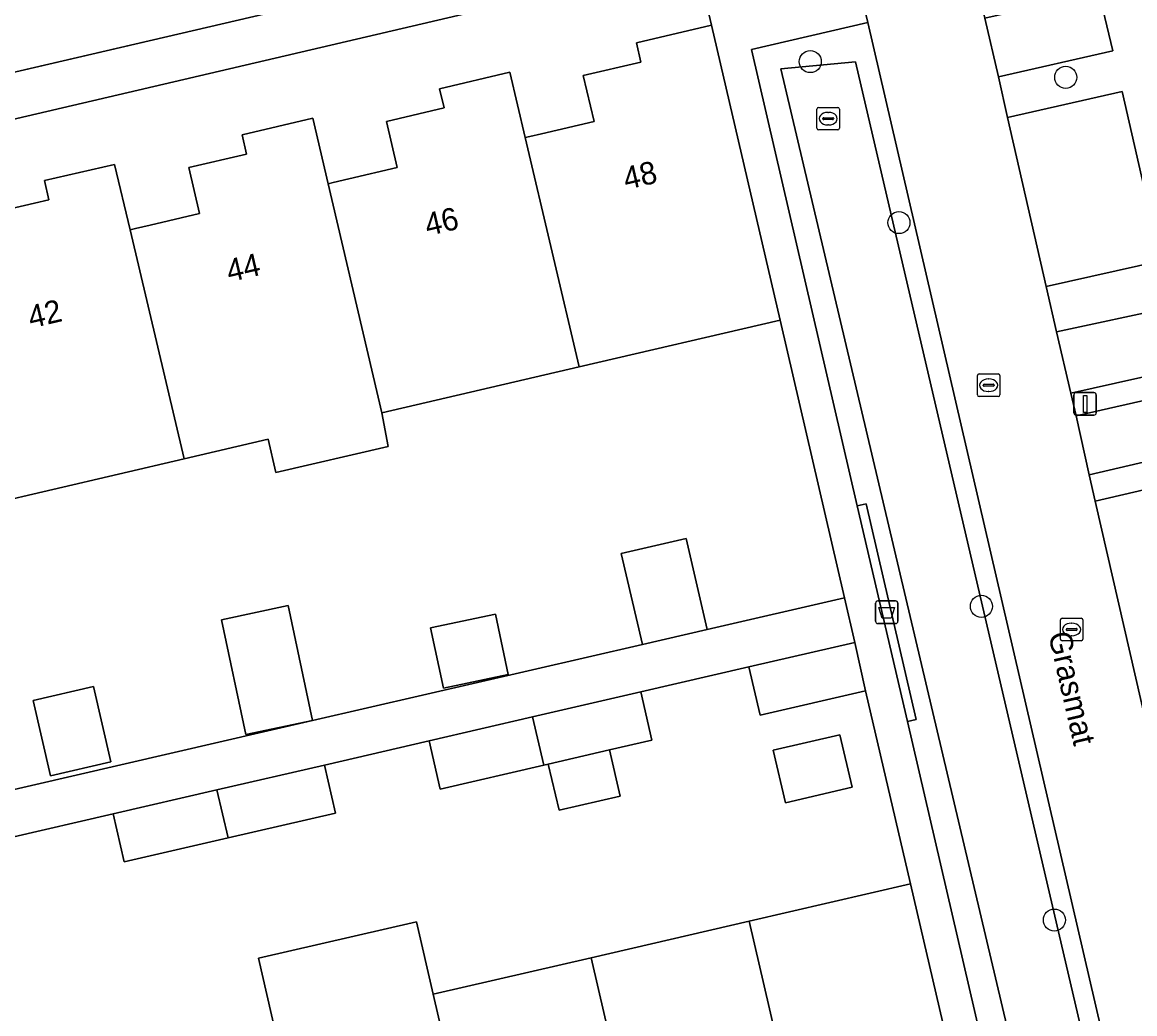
# Model space of a CAD drawing. Extents: x 156412 to 157779, y 382335 to 383768.
# Drawn here: x 156897.2 to 156946.58, y 382800.53 to 382844.52 of the extents above; entities that cross this region are included whole.
import ezdxf

# ---------------------------------------------------------------- set-up
doc = ezdxf.new("R2010")
doc.units = 0
for name, color, linetype in [('IMGEO_Afvalbak', 7, 'Continuous'), ('IMGEO_Berm_groen', 7, 'Continuous'), ('IMGEO_Boom', 7, 'Continuous'), ('IMGEO_Erf', 7, 'Continuous'), ('IMGEO_Greppel_droge_sloot', 7, 'Continuous'), ('IMGEO_Groenvoorziening', 7, 'Continuous'), ('IMGEO_Haag', 7, 'Continuous'), ('IMGEO_Kolk', 7, 'Continuous'), ('IMGEO_Lichtmast', 7, 'Continuous'), ('IMGEO_Muur', 7, 'Continuous'), ('IMGEO_Openbare_ruimte_label', 7, 'Continuous'), ('IMGEO_Pand', 7, 'Continuous'), ('IMGEO_Pand_nummerreeks', 7, 'Continuous'), ('IMGEO_Parkeervlak_open', 7, 'Continuous'), ('IMGEO_Rijbaan_lokaal_gesloten', 7, 'Continuous'), ('IMGEO_Rioolput', 7, 'Continuous'), ('IMGEO_Voetpad_open', 7, 'Continuous')]:
    doc.layers.add(name, color=color, linetype=linetype)

msp = doc.modelspace()

# ---------------------------------------------------------------- linework, layer by layer
at = {"layer": 'IMGEO_Afvalbak'}
for p, q in [((156935.078, 382817.947), (156935.078, 382818.747)), ((156935.078, 382818.747), (156935.078, 382817.947)), ((156935.178, 382818.847), (156935.968, 382818.847)), ((156935.968, 382818.847), (156935.178, 382818.847)), ((156936.068, 382818.747), (156936.068, 382817.947)), ((156936.068, 382817.947), (156936.068, 382818.747)), ((156935.968, 382817.847), (156935.178, 382817.847)), ((156935.178, 382817.847), (156935.968, 382817.847))]:
    msp.add_line(p, q, dxfattribs=at)
msp.add_lwpolyline([(156935.221, 382818.561), (156935.925, 382818.561), (156935.776, 382818.091), (156935.37, 382818.091), (156935.221, 382818.561)], dxfattribs=at)
for centre, start, end in [((156935.178, 382818.747), 90, 180), ((156935.178, 382818.747), 90, 180), ((156935.968, 382818.747), 0, 90), ((156935.968, 382818.747), 360, 90), ((156935.178, 382817.947), 180, 270), ((156935.178, 382817.947), 180, 270), ((156935.968, 382817.947), 270, 0), ((156935.968, 382817.947), 270, 0)]:
    msp.add_arc(centre, 0.1, start, end, dxfattribs=at)
at = {"layer": 'IMGEO_Berm_groen'}
for points in [[(156934.733, 382844.509), (156929.564, 382843.312), (156934.267, 382823.071), (156934.658, 382823.159), (156936.883, 382813.583), (156936.492, 382813.495), (156940.464, 382796.399), (156945.614, 382797.617)], [(156930.876, 382842.454), (156934.181, 382842.771), (156944.492, 382798.653), (156941.405, 382797.86)]]:
    msp.add_lwpolyline(points, close=True, dxfattribs=at)
at = {"layer": 'IMGEO_Boom'}
for centre in [(156932.178, 382842.779), (156943.519, 382842.081), (156936.113, 382835.634), (156939.776, 382818.609), (156943.014, 382804.691)]:
    msp.add_circle(centre, 0.489, dxfattribs=at)
at = {"layer": 'IMGEO_Erf'}
for points in [[(156895.822, 382836.05), (156898.385, 382836.643), (156898.186, 382837.5), (156901.301, 382838.221), (156901.988, 382835.311), (156902.231, 382835.368), (156902.877, 382835.519), (156905.075, 382836.033), (156904.597, 382838.078), (156907.158, 382838.676), (156906.957, 382839.533), (156910.101, 382840.268), (156910.781, 382837.356), (156911.003, 382837.408), (156911.695, 382837.571), (156913.846, 382838.076), (156913.366, 382840.12), (156915.927, 382840.721), (156915.726, 382841.578), (156918.85, 382842.311), (156919.531, 382839.405), (156919.736, 382839.453), (156920.242, 382839.571), (156922.58, 382840.117), (156922.103, 382842.162), (156924.664, 382842.759), (156924.464, 382843.616), (156927.788, 382844.392), (156927.114, 382847.315), (156859.126, 382831.425)], [(156908.428, 382799.782), (156907.686, 382802.997), (156914.697, 382804.615), (156915.442, 382801.401), (156922.45, 382803.019), (156929.471, 382804.64), (156936.631, 382806.293), (156934.638, 382814.868), (156929.95, 382813.781), (156929.454, 382815.919), (156924.651, 382814.81), (156925.145, 382812.672), (156923.265, 382812.238), (156923.74, 382810.192), (156921.026, 382809.562), (156920.55, 382811.611), (156920.351, 382811.565), (156915.752, 382810.503), (156915.259, 382812.64), (156910.611, 382811.566), (156911.103, 382809.434), (156906.335, 382808.333), (156901.729, 382807.27), (156901.237, 382809.4), (156896.638, 382808.337)]]:
    msp.add_lwpolyline(points, dxfattribs=at)
for points in [[(156923.79, 382820.948), (156926.665, 382821.615), (156927.6, 382817.588), (156933.697, 382818.983), (156930.84, 382831.306), (156921.915, 382829.231), (156913.155, 382827.194), (156913.44, 382825.7), (156908.457, 382824.541), (156908.113, 382826.021), (156904.385, 382825.154), (156895.625, 382823.117), (156886.866, 382821.08), (156878.096, 382819.04), (156869.326, 382817.001), (156860.401, 382814.925), (156862.355, 382806.461), (156865.257, 382807.132), (156866.124, 382803.38), (156910.089, 382813.546), (156924.725, 382816.92)], [(156910.089, 382813.546), (156907.132, 382812.917), (156906.049, 382818.014), (156909.006, 382818.642)], [(156915.323, 382817.649), (156918.204, 382818.262), (156918.773, 382815.585), (156915.892, 382814.972)], [(156897.681, 382814.428), (156900.359, 382815.046), (156901.129, 382811.711), (156898.452, 382811.093)], [(156930.537, 382812.225), (156933.494, 382812.911), (156934.035, 382810.581), (156931.078, 382809.895)]]:
    msp.add_lwpolyline(points, close=True, dxfattribs=at)
at = {"layer": 'IMGEO_Greppel_droge_sloot'}
msp.add_lwpolyline([(156941.405, 382797.86), (156944.492, 382798.653), (156934.181, 382842.771), (156930.876, 382842.454)], close=True, dxfattribs=at)
at = {"layer": 'IMGEO_Groenvoorziening'}
msp.add_lwpolyline([(156936.492, 382813.495), (156936.883, 382813.583), (156934.658, 382823.159), (156934.267, 382823.071)], close=True, dxfattribs=at)
at = {"layer": 'IMGEO_Haag'}
msp.add_lwpolyline([(156936.492, 382813.495), (156936.883, 382813.583), (156934.658, 382823.159), (156934.267, 382823.071)], close=True, dxfattribs=at)
at = {"layer": 'IMGEO_Kolk'}
for p, q in [((156932.55, 382840.748), (156933.402, 382840.748)), ((156932.475, 382839.822), (156932.475, 382840.674)), ((156932.734, 382840.242), (156932.734, 382840.254)), ((156932.777, 382840.291), (156933.175, 382840.291)), ((156932.963, 382840.528), (156932.988, 382840.528)), ((156933.218, 382840.254), (156933.218, 382840.242)), ((156933.476, 382840.674), (156933.476, 382839.822)), ((156933.172, 382840.205), (156932.774, 382840.205)), ((156932.986, 382839.968), (156932.961, 382839.968)), ((156933.402, 382839.748), (156932.55, 382839.748))]:
    msp.add_line(p, q, dxfattribs=at)
for points in [[(156932.55, 382840.748), (156933.402, 382840.748)], [(156932.475, 382839.822), (156932.475, 382840.674)], [(156933.476, 382840.674), (156933.476, 382839.822)], [(156933.402, 382839.748), (156932.55, 382839.748)]]:
    msp.add_lwpolyline(points, dxfattribs=at)
for centre, radius, start, end in [((156932.552, 382840.672), 0.0765, 91.552, 178.448), ((156932.552, 382840.672), 0.0765, 91.552, 178.448), ((156933.4, 382840.672), 0.0765, 1.552, 88.448), ((156933.4, 382840.672), 0.0765, 1.552, 88.448), ((156932.774, 382840.251), 0.0403, 85.8775, 175.7526), ((156933.179, 382840.253), 0.0386, 1.7309, 96.639), ((156932.552, 382839.824), 0.0765, 181.552, 268.448), ((156932.552, 382839.824), 0.0765, 181.552, 268.448), ((156932.771, 382840.241), 0.0366, 178.938, 274.7102), ((156933.175, 382840.248), 0.043, 264.8664, 352.4533), ((156933.4, 382839.824), 0.0765, 271.552, 358.448), ((156933.4, 382839.824), 0.0765, 271.552, 358.448)]:
    msp.add_arc(centre, radius, start, end, dxfattribs=at)
for centre, major_axis, ratio, start_param, end_param in [((156932.962, 382840.248), (-0.387, 0.002), 0.722429, 4.712389, 7.853982), ((156932.987, 382840.248), (-0.39, 0.002), 0.717154, 1.570796, 4.712389)]:
    msp.add_ellipse(centre, major_axis=major_axis, ratio=ratio, start_param=start_param, end_param=end_param, dxfattribs=at)
at = {"layer": 'IMGEO_Lichtmast'}
for p, q in [((156943.882, 382827.192), (156943.882, 382827.992)), ((156943.882, 382827.992), (156943.882, 382827.192)), ((156943.982, 382828.092), (156944.772, 382828.092)), ((156944.772, 382828.092), (156943.982, 382828.092)), ((156944.872, 382827.992), (156944.872, 382827.192)), ((156944.872, 382827.192), (156944.872, 382827.992)), ((156944.772, 382827.092), (156943.982, 382827.092)), ((156943.982, 382827.092), (156944.772, 382827.092))]:
    msp.add_line(p, q, dxfattribs=at)
msp.add_lwpolyline([(156944.302, 382827.967), (156944.452, 382827.967), (156944.452, 382827.217), (156944.302, 382827.217), (156944.302, 382827.967)], dxfattribs=at)
for centre, start, end in [((156943.982, 382827.992), 90, 180), ((156943.982, 382827.992), 90, 180), ((156944.772, 382827.992), 0, 90), ((156944.772, 382827.992), 360, 90), ((156943.982, 382827.192), 180, 270), ((156943.982, 382827.192), 180, 270), ((156944.772, 382827.192), 270, 0), ((156944.772, 382827.192), 270, 0)]:
    msp.add_arc(centre, 0.1, start, end, dxfattribs=at)
at = {"layer": 'IMGEO_Muur'}
for points in [[(156930.84, 382831.306), (156933.697, 382818.983)], [(156934.638, 382814.868), (156936.631, 382806.293)]]:
    msp.add_lwpolyline(points, dxfattribs=at)
at = {"layer": 'IMGEO_Pand'}
for points in [[(156927.788, 382844.392), (156924.464, 382843.616), (156924.664, 382842.759), (156922.103, 382842.162), (156922.58, 382840.117), (156920.242, 382839.571), (156919.736, 382839.453), (156919.531, 382839.405), (156921.915, 382829.231), (156930.84, 382831.306)], [(156919.531, 382839.405), (156918.85, 382842.311), (156915.726, 382841.578), (156915.927, 382840.721), (156913.366, 382840.12), (156913.846, 382838.076), (156911.695, 382837.571), (156911.003, 382837.408), (156910.781, 382837.356), (156913.155, 382827.194), (156921.915, 382829.231)], [(156910.781, 382837.356), (156910.101, 382840.268), (156906.957, 382839.533), (156907.158, 382838.676), (156904.597, 382838.078), (156905.075, 382836.033), (156902.877, 382835.519), (156902.231, 382835.368), (156901.988, 382835.311), (156904.385, 382825.154), (156908.113, 382826.021), (156908.457, 382824.541), (156913.44, 382825.7), (156913.155, 382827.194)], [(156901.988, 382835.311), (156901.301, 382838.221), (156898.186, 382837.5), (156898.385, 382836.643), (156895.822, 382836.05), (156896.296, 382834.004), (156894.3, 382833.542), (156893.451, 382833.345), (156893.227, 382833.293), (156895.625, 382823.117), (156904.385, 382825.154)], [(156924.725, 382816.92), (156927.6, 382817.588), (156926.665, 382821.615), (156923.79, 382820.948)], [(156910.089, 382813.546), (156909.006, 382818.642), (156906.049, 382818.014), (156907.132, 382812.917)], [(156915.323, 382817.649), (156915.892, 382814.972), (156918.773, 382815.585), (156918.204, 382818.262)], [(156929.454, 382815.919), (156929.95, 382813.781), (156934.638, 382814.868), (156934.158, 382817.006)], [(156897.681, 382814.428), (156898.452, 382811.093), (156901.129, 382811.711), (156900.359, 382815.046)], [(156924.651, 382814.81), (156919.855, 382813.702), (156920.351, 382811.565), (156920.55, 382811.611), (156923.265, 382812.238), (156925.145, 382812.672)], [(156919.855, 382813.702), (156915.259, 382812.64), (156915.752, 382810.503), (156920.351, 382811.565)], [(156930.537, 382812.225), (156931.078, 382809.895), (156934.035, 382810.581), (156933.494, 382812.911)], [(156923.265, 382812.238), (156920.55, 382811.611), (156921.026, 382809.562), (156923.74, 382810.192)], [(156905.843, 382810.464), (156906.335, 382808.333), (156911.103, 382809.434), (156910.611, 382811.566)], [(156905.843, 382810.464), (156901.237, 382809.4), (156901.729, 382807.27), (156906.335, 382808.333)], [(156929.471, 382804.64), (156931.509, 382795.84), (156933.258, 382796.243), (156934.83, 382796.606), (156935.508, 382793.675), (156939.348, 382794.6), (156936.631, 382806.293)], [(156915.442, 382801.401), (156914.697, 382804.615), (156907.686, 382802.997), (156908.428, 382799.782), (156911.144, 382788.058), (156914.816, 382788.933), (156914.145, 382791.833), (156915.777, 382792.21), (156917.48, 382792.603)], [(156922.45, 382803.019), (156925.163, 382791.326), (156928.862, 382792.176), (156928.191, 382795.074), (156929.822, 382795.45), (156931.509, 382795.84), (156929.471, 382804.64)], [(156915.442, 382801.401), (156917.48, 382792.603), (156919.26, 382793.013), (156920.832, 382793.376), (156921.502, 382790.484), (156925.163, 382791.326), (156922.45, 382803.019)]]:
    msp.add_lwpolyline(points, close=True, dxfattribs=at)
at = {"layer": 'IMGEO_Parkeervlak_open'}
for points in [[(156940.529, 382842.099), (156945.604, 382843.264), (156944.981, 382845.863), (156939.925, 382844.701)], [(156947.737, 382833.938), (156946.021, 382841.454), (156940.931, 382840.306), (156942.646, 382832.797)], [(156948.214, 382831.89), (156943.112, 382830.796), (156943.748, 382828.064), (156948.839, 382829.202)], [(156949.069, 382828.214), (156943.982, 382827.057), (156944.552, 382824.438), (156949.694, 382825.649)], [(156947.139, 382813.241), (156952.261, 382814.432), (156949.979, 382824.473), (156944.82, 382823.277)]]:
    msp.add_lwpolyline(points, close=True, dxfattribs=at)
at = {"layer": 'IMGEO_Rijbaan_lokaal_gesloten'}
for points in [[(156856.378, 382832.904), (156923.197, 382848.454), (156926.664, 382849.268), (156926.769, 382849.293)], [(156950.555, 382798.433), (156949.947, 382801.041), (156949.427, 382803.35), (156948.239, 382808.423), (156948.024, 382809.388), (156947.417, 382811.976), (156947.139, 382813.241), (156944.82, 382823.277), (156944.552, 382824.438), (156943.982, 382827.057), (156943.748, 382828.064), (156943.112, 382830.796), (156942.646, 382832.797), (156940.931, 382840.306), (156940.529, 382842.099), (156939.925, 382844.701), (156939.242, 382847.585)], [(156934.272, 382846.434), (156934.733, 382844.509), (156945.614, 382797.617), (156946.095, 382795.544)]]:
    msp.add_lwpolyline(points, dxfattribs=at)
at = {"layer": 'IMGEO_Rioolput'}
for p, q in [((156939.672, 382828.92), (156940.524, 382828.92)), ((156939.597, 382827.994), (156939.597, 382828.846)), ((156939.856, 382828.414), (156939.856, 382828.426)), ((156939.899, 382828.463), (156940.297, 382828.463)), ((156940.085, 382828.7), (156940.11, 382828.7)), ((156940.34, 382828.426), (156940.34, 382828.414)), ((156940.598, 382828.846), (156940.598, 382827.994)), ((156940.524, 382827.92), (156939.672, 382827.92)), ((156940.294, 382828.377), (156939.896, 382828.377)), ((156940.108, 382828.14), (156940.083, 382828.14)), ((156943.356, 382818.083), (156944.208, 382818.083)), ((156943.281, 382817.157), (156943.281, 382818.009)), ((156943.54, 382817.577), (156943.54, 382817.589)), ((156943.978, 382817.54), (156943.58, 382817.54)), ((156943.583, 382817.626), (156943.981, 382817.626)), ((156943.769, 382817.863), (156943.794, 382817.863)), ((156944.024, 382817.589), (156944.024, 382817.577)), ((156944.282, 382818.009), (156944.282, 382817.157)), ((156944.208, 382817.083), (156943.356, 382817.083)), ((156943.792, 382817.303), (156943.767, 382817.303))]:
    msp.add_line(p, q, dxfattribs=at)
for points in [[(156939.672, 382828.92), (156940.524, 382828.92)], [(156939.597, 382827.994), (156939.597, 382828.846)], [(156940.598, 382828.846), (156940.598, 382827.994)], [(156940.524, 382827.92), (156939.672, 382827.92)], [(156943.356, 382818.083), (156944.208, 382818.083)], [(156943.281, 382817.157), (156943.281, 382818.009)], [(156944.282, 382818.009), (156944.282, 382817.157)], [(156944.208, 382817.083), (156943.356, 382817.083)]]:
    msp.add_lwpolyline(points, dxfattribs=at)
for centre, radius, start, end in [((156939.674, 382828.844), 0.0765, 91.552, 178.448), ((156939.674, 382828.844), 0.0765, 91.552, 178.448), ((156940.522, 382828.844), 0.0765, 1.552, 88.448), ((156940.522, 382828.844), 0.0765, 1.552, 88.448), ((156939.896, 382828.423), 0.0403, 85.8775, 175.7526), ((156939.893, 382828.413), 0.0366, 178.938, 274.7102), ((156940.297, 382828.42), 0.043, 264.8664, 352.4533), ((156940.301, 382828.425), 0.0386, 1.7309, 96.639), ((156939.674, 382827.996), 0.0765, 181.552, 268.448), ((156939.674, 382827.996), 0.0765, 181.552, 268.448), ((156940.522, 382827.996), 0.0765, 271.552, 358.448), ((156940.522, 382827.996), 0.0765, 271.552, 358.448), ((156943.358, 382818.007), 0.0765, 91.552, 178.448), ((156943.358, 382818.007), 0.0765, 91.552, 178.448), ((156944.206, 382818.007), 0.0765, 1.552, 88.448), ((156944.206, 382818.007), 0.0765, 1.552, 88.448), ((156943.58, 382817.586), 0.0403, 85.8775, 175.7526), ((156943.577, 382817.576), 0.0366, 178.938, 274.7102), ((156943.981, 382817.583), 0.043, 264.8664, 352.4533), ((156943.985, 382817.588), 0.0386, 1.7309, 96.639), ((156943.358, 382817.159), 0.0765, 181.552, 268.448), ((156943.358, 382817.159), 0.0765, 181.552, 268.448), ((156944.206, 382817.159), 0.0765, 271.552, 358.448), ((156944.206, 382817.159), 0.0765, 271.552, 358.448)]:
    msp.add_arc(centre, radius, start, end, dxfattribs=at)
for centre, major_axis, ratio, start_param, end_param in [((156940.084, 382828.42), (-0.387, 0.002), 0.722429, 4.712389, 7.853982), ((156940.109, 382828.42), (-0.39, 0.002), 0.717154, 1.570796, 4.712389), ((156943.768, 382817.583), (-0.387, 0.002), 0.722429, 4.712389, 7.853982), ((156943.793, 382817.583), (-0.39, 0.002), 0.717154, 1.570796, 4.712389)]:
    msp.add_ellipse(centre, major_axis=major_axis, ratio=ratio, start_param=start_param, end_param=end_param, dxfattribs=at)
at = {"layer": 'IMGEO_Voetpad_open'}
for points in [[(156852.727, 382829.996), (156854.08, 382830.294), (156856.714, 382830.844), (156856.91, 382830.891), (156859.126, 382831.425), (156927.114, 382847.315), (156926.664, 382849.268), (156923.197, 382848.454), (156856.378, 382832.904), (156817.084, 382823.811), (156780.281, 382815.295), (156707.464, 382798.538), (156707.908, 382796.596), (156778.432, 382812.831), (156780.962, 382813.412), (156782.34, 382813.73)], [(156901.237, 382809.4), (156905.843, 382810.464), (156910.611, 382811.566), (156915.259, 382812.64), (156919.855, 382813.702), (156924.651, 382814.81), (156929.454, 382815.919), (156934.158, 382817.006), (156933.697, 382818.983), (156927.6, 382817.588), (156924.725, 382816.92), (156910.089, 382813.546), (156866.124, 382803.38), (156863.234, 382802.713), (156863.704, 382800.728), (156868.402, 382801.813), (156873.186, 382802.919), (156877.753, 382803.974), (156882.588, 382805.091), (156887.245, 382806.167), (156891.793, 382807.218), (156896.638, 382808.337)]]:
    msp.add_lwpolyline(points, close=True, dxfattribs=at)
for points in [[(156926.769, 382849.293), (156926.664, 382849.268), (156927.114, 382847.315), (156927.788, 382844.392), (156930.84, 382831.306), (156933.697, 382818.983), (156934.158, 382817.006), (156934.638, 382814.868), (156936.631, 382806.293), (156939.348, 382794.6), (156940.042, 382791.626), (156940.449, 382789.73), (156942.475, 382790.198), (156941.885, 382792.632), (156940.464, 382796.399), (156936.492, 382813.495), (156934.267, 382823.071), (156929.564, 382843.312), (156934.733, 382844.509), (156934.272, 382846.434)], [(156942.115, 382848.3), (156939.242, 382847.585), (156939.925, 382844.701), (156944.981, 382845.863), (156945.604, 382843.264), (156940.529, 382842.099), (156940.931, 382840.306), (156946.021, 382841.454), (156947.737, 382833.938), (156942.646, 382832.797), (156943.112, 382830.796), (156948.214, 382831.89)], [(156948.839, 382829.202), (156943.748, 382828.064), (156943.982, 382827.057), (156949.069, 382828.214)], [(156949.694, 382825.649), (156944.552, 382824.438), (156944.82, 382823.277), (156949.979, 382824.473)]]:
    msp.add_lwpolyline(points, dxfattribs=at)

# ---------------------------------------------------------------- texts
at = {"layer": 'IMGEO_Openbare_ruimte_label'}
msp.add_text('Grasmat', height=1, rotation=282.9388, dxfattribs=at).set_placement((156942.738, 382817.37))
at = {"layer": 'IMGEO_Pand_nummerreeks'}
for s, p in [('48', (156924.005, 382837.085)), ('46', (156915.197, 382835.036)), ('44', (156906.393, 382832.987)), ('42', (156897.586, 382830.938))]:
    msp.add_text(s, height=1, rotation=13.0978, dxfattribs=at).set_placement(p)

doc.saveas('drawing.dxf')
